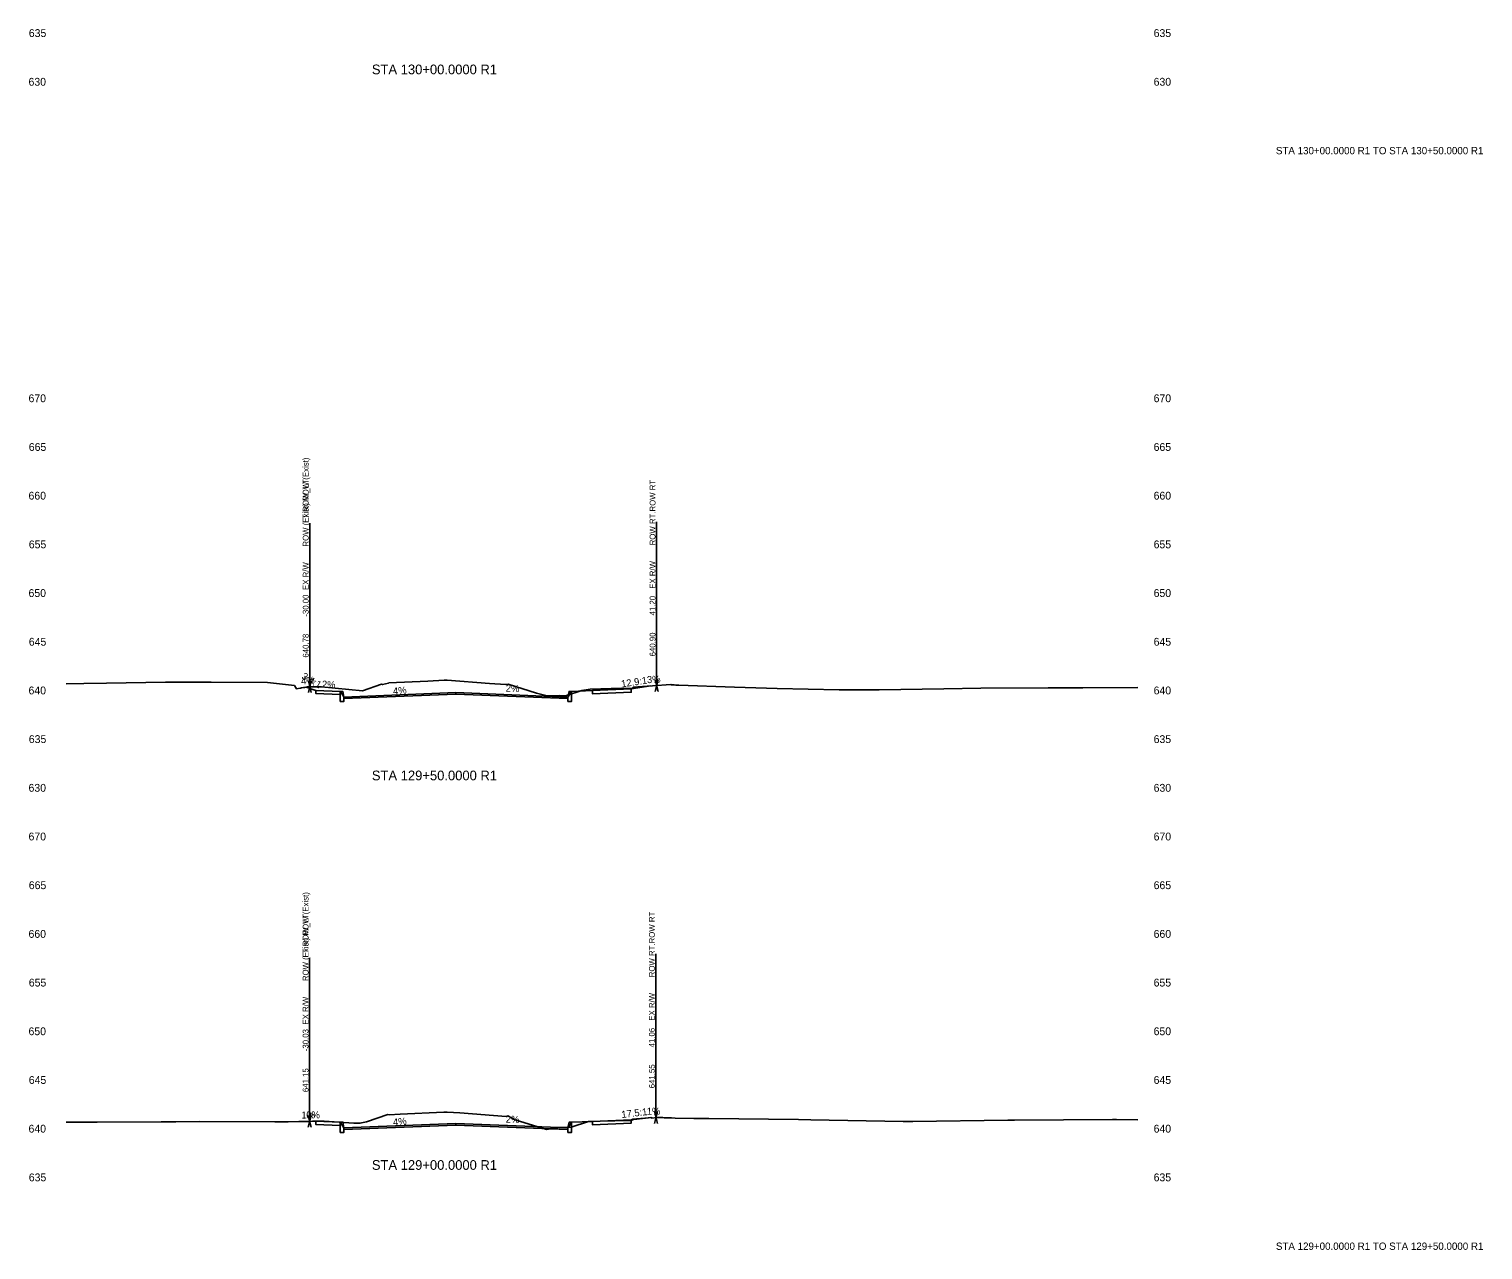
# Model space of a CAD drawing. Extents: x 2 to 741, y 16 to 2207.
# Drawn here: x 442.4 to 740.8, y 15.9 to 266.6 of the extents above; entities that cross this region are included whole.
import ezdxf

# ---------------------------------------------------------------- set-up
doc = ezdxf.new("R2010")
doc.units = 0
for name, color, linetype in [('BORD_text_large_2', 7, 'Continuous'), ('Draft_XS_Feature_Name', 7, 'Continuous'), ('Draft_XS_Label', 7, 'Continuous'), ('Draft_XS_Point_Label_Indicator', 7, 'Continuous'), ('Draft_XS_Terminator', 7, 'Continuous'), ('Draft_XS_Text', 7, 'Continuous'), ('E_ROW', 7, 'Continuous'), ('E_Terrain_Exterior', 7, 'Continuous'), ('E_Terrain_Points_Low', 7, 'Continuous'), ('Grade_Veg_Grass', 7, 'Continuous'), ('P_XS_Sections', 7, 'Continuous'), ('Road_Curb', 7, 'Continuous'), ('Road_Pave_Asphalt', 7, 'Continuous'), ('Road_Sidewalk', 7, 'Continuous'), ('Terrain_Design', 7, 'Continuous')]:
    doc.layers.add(name, color=color, linetype=linetype)

msp = doc.modelspace()

# ---------------------------------------------------------------- linework, layer by layer
at = {"layer": 'Draft_XS_Terminator'}
for p, q in [((500, 131.55), (500, 153.55)), ((500, 131.55), (500, 153.55)), ((571.2, 131.8), (571.2, 153.8)), ((499.97, 42.31), (499.97, 64.31)), ((499.97, 42.31), (499.97, 64.31)), ((571.06, 43.1), (571.06, 65.1))]:
    msp.add_line(p, q, dxfattribs=at)
at = {"layer": 'E_ROW'}
for p, q in [((500, 131.55), (500, 165.15)), ((500, 131.55), (500, 165.15)), ((571.2, 131.8), (571.2, 165.4)), ((499.7, 130.35), (500.3, 132.75)), ((499.7, 132.75), (500.3, 130.35)), ((499.7, 130.35), (500.3, 132.75)), ((499.7, 132.75), (500.3, 130.35)), ((570.9, 130.6), (571.5, 133)), ((570.9, 133), (571.5, 130.6)), ((499.97, 42.31), (499.97, 75.91)), ((499.97, 42.31), (499.97, 75.91)), ((571.06, 43.1), (571.06, 76.7)), ((499.67, 41.11), (500.27, 43.51)), ((499.67, 43.51), (500.27, 41.11)), ((499.67, 41.11), (500.27, 43.51)), ((499.67, 43.51), (500.27, 41.11)), ((570.76, 41.9), (571.36, 44.3)), ((570.76, 44.3), (571.36, 41.9))]:
    msp.add_line(p, q, dxfattribs=at)
at = {"layer": 'E_Terrain_Exterior'}
for points in [[(450, 132.18), (453.6, 132.23), (458.26, 132.29), (470.36, 132.47), (479.74, 132.5), (491.29, 132.41), (496.85, 131.85), (497.25, 131.14), (498.02, 131.27), (498.07, 131.28), (498.32, 131.33), (498.74, 131.4), (498.79, 131.41), (498.85, 131.42), (498.97, 131.44), (499.33, 131.51), (499.56, 131.55), (499.58, 131.55), (502.4, 131.55), (510.82, 130.72), (514.73, 132.06), (514.94, 132), (516.13, 132.33), (516.23, 132.37), (524.23, 132.73), (527.58, 132.91), (527.67, 132.91), (527.98, 132.91), (528.13, 132.93), (528.23, 132.92), (536.9, 132.26), (540.26, 132.02), (540.46, 132), (540.72, 132.09), (546.57, 130.27), (548.72, 129.68), (551.24, 129.75), (552.52, 129.71), (555.81, 130.8), (557.53, 131.08), (564.05, 131.25), (566.15, 131.22), (566.34, 131.37), (566.41, 131.46), (569.23, 131.7), (570.32, 131.74), (574.1, 132), (574.24, 131.99), (574.47, 131.96), (574.61, 131.95), (574.66, 131.95), (574.78, 131.93), (575.15, 131.89), (575.16, 131.89), (575.77, 131.87), (587.16, 131.46), (595.93, 131.18), (608.64, 130.96), (616.86, 130.96), (630.12, 131.15), (637.78, 131.24), (651.6, 131.35), (658.71, 131.37), (670, 131.39)], [(450, 42.13), (456.34, 42.13), (469.48, 42.18), (471.44, 42.19), (472.51, 42.21), (477.27, 42.3), (492.81, 42.2), (492.92, 42.2), (495.55, 42.23), (497.72, 42.27), (499.16, 42.3), (499.23, 42.3), (499.29, 42.3), (500.09, 42.31), (500.58, 42.32), (500.64, 42.32), (500.71, 42.32), (500.92, 42.33), (501.03, 42.33), (501.27, 42.33), (501.32, 42.33), (501.37, 42.33), (501.54, 42.34), (501.66, 42.34), (502.95, 42.37), (509.07, 41.94), (510.29, 41.92), (511.61, 42.2), (516.03, 43.71), (516.26, 43.65), (518.57, 43.77), (527.5, 44.17), (528.02, 44.18), (528.17, 44.18), (530.77, 44.05), (540.3, 43.32), (540.39, 43.33), (540.67, 43.42), (542.19, 42.64), (548.58, 40.66), (549.4, 40.74), (550.9, 41.03), (553.65, 41.1), (557.21, 42.28), (559.6, 42.34), (565.66, 42.51), (565.99, 42.42), (566.17, 42.56), (566.22, 42.74), (568.79, 42.95), (568.93, 42.95), (570.15, 43.08), (570.21, 42.98), (571.23, 43.12), (571.28, 43.12), (571.35, 43.12), (571.42, 43.11), (571.44, 43.11), (571.5, 43.11), (571.61, 43.11), (571.73, 43.1), (571.75, 43.1), (571.79, 43.1), (571.86, 43.1), (571.99, 43.09), (572.01, 43.09), (572.06, 43.09), (572.21, 43.08), (572.44, 43.08), (572.73, 43.06), (573.1, 43.05), (573.6, 43.03), (574.28, 43.01), (574.97, 42.98), (578.85, 42.91), (579.62, 42.9), (581.91, 42.9), (600.33, 42.69), (602.83, 42.62), (621.82, 42.3), (623.76, 42.31), (643.3, 42.54), (644.69, 42.56), (664.78, 42.66), (665.62, 42.67), (670, 42.63)]]:
    msp.add_lwpolyline(points, dxfattribs=at)
at = {"layer": 'Grade_Veg_Grass'}
for points in [[(499.25, 131.49), (501.25, 130.82), (501.25, 130.82)], [(570, 131.73), (566, 131.11), (566, 131.11)], [(553.75, 130.62), (558, 130.79)], [(499.25, 42.3), (501.25, 42.32), (501.25, 42.32)], [(553.75, 42.12), (558, 42.29)], [(570, 43.07), (566, 42.61), (566, 42.61)]]:
    msp.add_lwpolyline(points, dxfattribs=at)
at = {"layer": 'Road_Curb'}
for points in [[(507, 129.45), (507, 128.54), (506.25, 128.54), (506.25, 130.62), (506.77, 130.62), (507, 129.45)], [(553, 129.45), (553, 128.54), (553.75, 128.54), (553.75, 130.62), (553.23, 130.62), (553, 129.45)], [(507, 40.95), (507, 40.04), (506.25, 40.04), (506.25, 42.12), (506.77, 42.12), (507, 40.95)], [(553, 40.95), (553, 40.04), (553.75, 40.04), (553.75, 42.12), (553.23, 42.12), (553, 40.95)]]:
    msp.add_lwpolyline(points, dxfattribs=at)
at = {"layer": 'Road_Pave_Asphalt'}
for points in [[(530, 130.37), (530, 130.04), (507, 129.12), (507, 129.45), (530, 130.37)], [(530, 130.37), (530, 130.04), (553, 129.12), (553, 129.45), (530, 130.37)], [(530, 41.87), (530, 41.54), (507, 40.62), (507, 40.95), (530, 41.87)], [(530, 41.87), (530, 41.54), (553, 40.62), (553, 40.95), (530, 41.87)]]:
    msp.add_lwpolyline(points, dxfattribs=at)
at = {"layer": 'Road_Sidewalk'}
for points in [[(506.25, 130.62), (506.25, 129.95), (501.25, 130.15), (501.25, 130.82), (506.25, 130.62)], [(558, 130.79), (558, 130.12), (566, 130.44), (566, 131.11), (558, 130.79)], [(506.25, 42.12), (506.25, 41.45), (501.25, 41.65), (501.25, 42.32), (506.25, 42.12)], [(558, 42.29), (558, 41.62), (566, 41.94), (566, 42.61), (558, 42.29)]]:
    msp.add_lwpolyline(points, dxfattribs=at)
at = {"layer": 'Terrain_Design'}
for points in [[(499.25, 131.49), (499.25, 131.49), (501.25, 130.82), (506.25, 130.62), (506.77, 130.62), (507, 129.45), (530, 130.37), (553, 129.45), (553.23, 130.62), (553.75, 130.62), (558, 130.79), (566, 131.11), (570, 131.73)], [(499.25, 131.49), (499.25, 131.49), (501.25, 130.82), (506.25, 130.62), (506.77, 129.81), (507, 129.45), (530, 130.37), (553, 129.45), (553.23, 129.81), (553.75, 130.62), (558, 130.79), (566, 131.11), (570, 131.73)], [(499.25, 42.3), (499.25, 42.3), (501.25, 42.32), (506.25, 42.12), (506.77, 42.12), (507, 40.95), (530, 41.87), (553, 40.95), (553.23, 42.12), (553.75, 42.12), (558, 42.29), (566, 42.61), (570, 43.07)], [(499.25, 42.3), (499.25, 42.3), (501.25, 42.32), (506.25, 42.12), (506.77, 41.31), (507, 40.95), (530, 41.87), (553, 40.95), (553.23, 41.31), (553.75, 42.12), (558, 42.29), (566, 42.61), (570, 43.07)]]:
    msp.add_lwpolyline(points, dxfattribs=at)

# ---------------------------------------------------------------- texts
at = {"layer": 'BORD_text_large_2'}
for s, p in [('STA 130+00.0000 R1 TO STA 130+50.0000 R1', (698.32, 240.92)), ('STA 129+00.0000 R1 TO STA 129+50.0000 R1', (698.32, 15.92))]:
    msp.add_text(s, height=1.5, dxfattribs=at).set_placement(p)
at = {"layer": 'Draft_XS_Feature_Name'}
for s, p in [('ROW (Exist).ROW (Exist)', (499.76, 160.35)), ('ROW_LT.ROW_LT', (499.76, 160.35)), ('ROW RT.ROW RT', (570.96, 160.6)), ('ROW (Exist).ROW (Exist)', (499.73, 71.11)), ('ROW_LT.ROW_LT', (499.73, 71.11)), ('ROW RT.ROW RT', (570.82, 71.9))]:
    msp.add_text(s, height=1.2, rotation=90, dxfattribs=at).set_placement(p)
at = {"layer": 'Draft_XS_Label'}
for s, p in [('-30.00', (499.76, 145.95)), ('-30.00', (499.76, 145.95)), ('41.20', (570.96, 146.2)), ('640.78', (499.76, 137.55)), ('640.78', (499.76, 137.55)), ('640.90', (570.96, 137.8)), ('-30.03', (499.73, 56.71)), ('-30.03', (499.73, 56.71)), ('41.06', (570.82, 57.5)), ('641.55', (570.82, 49.1)), ('641.15', (499.73, 48.31)), ('641.15', (499.73, 48.31))]:
    msp.add_text(s, height=1.2, rotation=90, dxfattribs=at).set_placement(p)
at = {"layer": 'Draft_XS_Point_Label_Indicator'}
for p in [(499.24, 131.48), (569.99, 131.72), (501.24, 130.81), (506.24, 130.61), (506.76, 130.61), (506.99, 129.44), (506.99, 128.52), (552.99, 129.44), (552.99, 128.52), (553.22, 130.61), (553.74, 130.61), (557.99, 130.78), (565.99, 131.1), (499.24, 42.28), (501.24, 42.31), (506.24, 42.11), (506.76, 42.11), (553.22, 42.11), (553.74, 42.11), (557.99, 42.28), (565.99, 42.6), (569.99, 43.05), (506.99, 40.94), (506.99, 40.02), (552.99, 40.94), (552.99, 40.02)]:
    msp.add_text('X', height=0.024, dxfattribs=at).set_placement(p)
at = {"layer": 'Draft_XS_Text'}
for s, height, p in [('635', 1.608, (442.32, 265)), ('635', 1.608, (673.22, 265)), ('STA 130+00.0000 R1', 1.992, (512.74, 257.35)), ('630', 1.608, (442.26, 255)), ('630', 1.608, (673.22, 255)), ('670', 1.608, (442.26, 190)), ('670', 1.608, (673.22, 190)), ('665', 1.608, (442.32, 180)), ('665', 1.608, (673.22, 180)), ('660', 1.608, (442.26, 170)), ('660', 1.608, (673.22, 170)), ('655', 1.608, (442.32, 160)), ('655', 1.608, (673.22, 160)), ('650', 1.608, (442.26, 150)), ('650', 1.608, (673.22, 150)), ('645', 1.608, (442.32, 140)), ('645', 1.608, (673.22, 140)), ('640', 1.608, (442.26, 130)), ('640', 1.608, (673.22, 130)), ('635', 1.608, (442.32, 120)), ('635', 1.608, (673.22, 120)), ('STA 129+50.0000 R1', 1.992, (512.74, 112.35)), ('630', 1.608, (442.26, 110)), ('630', 1.608, (673.22, 110)), ('670', 1.608, (442.26, 100)), ('670', 1.608, (673.22, 100)), ('665', 1.608, (442.32, 90)), ('665', 1.608, (673.22, 90)), ('660', 1.608, (442.26, 80)), ('660', 1.608, (673.22, 80)), ('655', 1.608, (442.32, 70)), ('655', 1.608, (673.22, 70)), ('650', 1.608, (442.26, 60)), ('650', 1.608, (673.22, 60)), ('645', 1.608, (442.32, 50)), ('645', 1.608, (673.22, 50)), ('640', 1.608, (442.26, 40)), ('640', 1.608, (673.22, 40)), ('STA 129+00.0000 R1', 1.992, (512.74, 32.35)), ('635', 1.608, (442.32, 30)), ('635', 1.608, (673.22, 30))]:
    msp.add_text(s, height=height, dxfattribs=at).set_placement(p)
for s, rotation, p in [('3.4:1', 329.6701, (498.17, 133.32)), ('4%', 4.4483, (498.27, 132.02)), ('2%', 357.7094, (502.46, 131.37)), ('4%', 4.5657, (517.14, 129.95)), ('2%', 357.7094, (540.21, 130.57)), ('12.9:1', 8.7991, (564.04, 131.41)), ('3%', 3.495, (569.25, 132.28)), ('17.5:1', 6.5164, (564.04, 42.99)), ('1%', 1.6607, (569.2, 43.64)), ('1%', 1.0059, (498.29, 42.88)), ('0%', 0.4465, (499.29, 42.9)), ('4%', 4.5657, (517.14, 41.45)), ('2%', 357.7094, (540.21, 42.07))]:
    msp.add_text(s, height=1.44, rotation=rotation, dxfattribs=at).set_placement(p)
at = {"layer": 'E_ROW'}
for p in [(499.76, 151.43), (499.76, 151.43), (570.96, 151.68), (570.82, 62.98), (499.73, 62.19), (499.73, 62.19)]:
    msp.add_text('EX R/W', height=1.2, rotation=90, dxfattribs=at).set_placement(p)
at = {"layer": 'E_Terrain_Points_Low'}
for p in [(529.99, 130.36), (529.99, 41.86)]:
    msp.add_text('X', height=0.024, dxfattribs=at).set_placement(p)
at = {"layer": 'P_XS_Sections'}
for p in [(450, 255), (450, 110), (450, 30)]:
    msp.add_text('-', height=0.0001, dxfattribs=at).set_placement(p)

doc.saveas('drawing.dxf')
